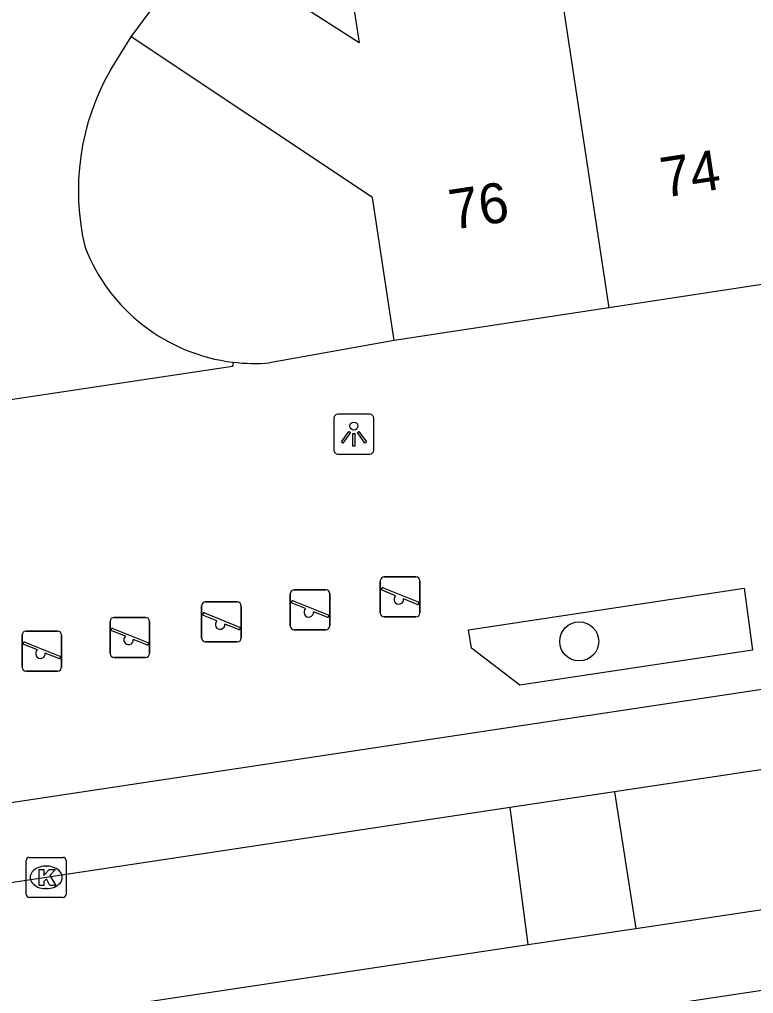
# Model space of a CAD drawing. Extents: x 159280 to 160375, y 384531 to 385872.
# Drawn here: x 159751.21 to 159769.6, y 384897.02 to 384921.41 of the extents above; entities that cross this region are included whole.
import ezdxf

# ---------------------------------------------------------------- set-up
doc = ezdxf.new("R2010")
doc.units = 0
for name, color, linetype in [('IMGEO_Boom', 7, 'Continuous'), ('IMGEO_Kolk', 7, 'Continuous'), ('IMGEO_Lichtpunt', 7, 'Continuous'), ('IMGEO_Pand', 7, 'Continuous'), ('IMGEO_Pand_nummerreeks', 7, 'Continuous'), ('IMGEO_Rijbaan_lokaal_open', 7, 'Continuous'), ('IMGEO_Speelvoorziening', 7, 'Continuous'), ('IMGEO_Voetpad_open', 7, 'Continuous')]:
    doc.layers.add(name, color=color, linetype=linetype)

msp = doc.modelspace()

# ---------------------------------------------------------------- linework, layer by layer
at = {"layer": 'IMGEO_Boom'}
msp.add_circle((159765.234, 384905.833), 0.489, dxfattribs=at)
at = {"layer": 'IMGEO_Kolk'}
for p, q in [((159751.383, 384899.5), (159751.383, 384900.352)), ((159751.458, 384900.426), (159752.31, 384900.426)), ((159752.384, 384900.352), (159752.384, 384899.5)), ((159751.871, 384900.206), (159751.896, 384900.206)), ((159751.894, 384899.646), (159751.869, 384899.646)), ((159752.31, 384899.426), (159751.458, 384899.426))]:
    msp.add_line(p, q, dxfattribs=at)
for points in [[(159751.383, 384899.5), (159751.383, 384900.352)], [(159751.458, 384900.426), (159752.31, 384900.426)], [(159752.384, 384900.352), (159752.384, 384899.5)], [(159751.704, 384900.126), (159751.827, 384900.126), (159751.827, 384899.975), (159751.957, 384900.126), (159752.121, 384900.126), (159751.975, 384899.975), (159752.128, 384899.726), (159751.976, 384899.726), (159751.891, 384899.89), (159751.827, 384899.823), (159751.827, 384899.726), (159751.704, 384899.726), (159751.704, 384900.126)], [(159752.31, 384899.426), (159751.458, 384899.426)]]:
    msp.add_lwpolyline(points, dxfattribs=at)
for centre, start, end in [((159751.46, 384900.35), 91.552, 178.448), ((159751.46, 384900.35), 91.552, 178.448), ((159752.308, 384900.35), 1.552, 88.448), ((159752.308, 384900.35), 1.552, 88.448), ((159751.46, 384899.502), 181.552, 268.448), ((159751.46, 384899.502), 181.552, 268.448), ((159752.308, 384899.502), 271.552, 358.448), ((159752.308, 384899.502), 271.552, 358.448)]:
    msp.add_arc(centre, 0.0765, start, end, dxfattribs=at)
for centre, major_axis, ratio, start_param, end_param in [((159751.87, 384899.926), (-0.387, 0.002), 0.722429, 4.712389, 7.853982), ((159751.895, 384899.926), (-0.39, 0.002), 0.717154, 1.570796, 4.712389)]:
    msp.add_ellipse(centre, major_axis=major_axis, ratio=ratio, start_param=start_param, end_param=end_param, dxfattribs=at)
at = {"layer": 'IMGEO_Lichtpunt'}
for p, q in [((159759.994, 384911.522), (159759.186, 384911.522)), ((159759.994, 384911.522), (159759.186, 384911.522)), ((159759.092, 384911.427), (159759.092, 384910.62)), ((159759.092, 384911.427), (159759.092, 384910.62)), ((159760.088, 384910.62), (159760.088, 384911.427)), ((159760.088, 384910.62), (159760.088, 384911.427)), ((159759.186, 384910.526), (159759.994, 384910.526)), ((159759.186, 384910.526), (159759.994, 384910.526))]:
    msp.add_line(p, q, dxfattribs=at)
for points in [[(159759.466, 384911.091), (159759.505, 384911.063), (159759.317, 384910.801), (159759.279, 384910.828), (159759.466, 384911.091)], [(159759.568, 384911.043), (159759.615, 384911.043), (159759.615, 384910.721), (159759.568, 384910.721), (159759.568, 384911.043)], [(159759.678, 384911.063), (159759.716, 384911.09), (159759.903, 384910.828), (159759.864, 384910.8), (159759.678, 384911.063)]]:
    msp.add_lwpolyline(points, dxfattribs=at)
msp.add_circle((159759.591, 384911.225), 0.0994, dxfattribs=at)
for centre, start, end in [((159759.186, 384911.427), 90, 180), ((159759.186, 384911.427), 90, 180), ((159759.994, 384911.427), 0, 90), ((159759.994, 384911.427), 0, 90), ((159759.186, 384910.62), 180, 270), ((159759.186, 384910.62), 180, 270), ((159759.994, 384910.62), 270, 0), ((159759.994, 384910.62), 270, 360)]:
    msp.add_arc(centre, 0.0946, start, end, dxfattribs=at)
at = {"layer": 'IMGEO_Pand'}
for points in [[(159764.393, 384924.608), (159764.205, 384924.579), (159759.261, 384923.827), (159759.719, 384920.818), (159755.775, 384923.361)], [(159764.393, 384924.608), (159764.83, 384921.733), (159765.976, 384914.186)], [(159754.013, 384920.967), (159755.775, 384923.361)], [(159760.601, 384913.369), (159760.056, 384916.949), (159754.013, 384920.967)], [(159771.234, 384914.986), (159765.976, 384914.186)], [(159765.976, 384914.186), (159760.601, 384913.369)]]:
    msp.add_lwpolyline(points, dxfattribs=at)
at = {"layer": 'IMGEO_Rijbaan_lokaal_open'}
for points in [[(159766.651, 384898.646), (159819.621, 384906.592)], [(159790.937, 384905.799), (159766.12, 384902.067)], [(159766.12, 384902.067), (159763.502, 384901.673)], [(159766.12, 384902.067), (159766.651, 384898.646)], [(159763.502, 384901.673), (159747.895, 384899.326)], [(159763.958, 384898.242), (159763.502, 384901.673)], [(159763.958, 384898.242), (159766.651, 384898.646)], [(159743.377, 384895.154), (159763.958, 384898.242)]]:
    msp.add_lwpolyline(points, dxfattribs=at)
at = {"layer": 'IMGEO_Speelvoorziening'}
for p, q in [((159760.253, 384906.549), (159760.253, 384907.349)), ((159760.253, 384907.349), (159760.253, 384906.549)), ((159760.353, 384907.449), (159761.143, 384907.449)), ((159761.143, 384907.449), (159760.353, 384907.449)), ((159761.243, 384907.349), (159761.243, 384906.549)), ((159761.243, 384906.549), (159761.243, 384907.349)), ((159758.098, 384907.127), (159758.888, 384907.127)), ((159758.888, 384907.127), (159758.098, 384907.127)), ((159760.636, 384906.977), (159760.297, 384907.114)), ((159760.322, 384907.174), (159761.198, 384906.821)), ((159755.878, 384906.821), (159756.668, 384906.821)), ((159756.668, 384906.821), (159755.878, 384906.821)), ((159757.998, 384906.227), (159757.998, 384907.027)), ((159757.998, 384907.027), (159757.998, 384906.227)), ((159758.067, 384906.852), (159758.943, 384906.499)), ((159758.988, 384907.027), (159758.988, 384906.227)), ((159758.988, 384906.227), (159758.988, 384907.027)), ((159761.174, 384906.761), (159760.834, 384906.898)), ((159755.778, 384905.921), (159755.778, 384906.721)), ((159755.778, 384906.721), (159755.778, 384905.921)), ((159756.768, 384906.721), (159756.768, 384905.921)), ((159756.768, 384905.921), (159756.768, 384906.721)), ((159758.381, 384906.655), (159758.042, 384906.792)), ((159758.919, 384906.439), (159758.579, 384906.576)), ((159753.484, 384905.535), (159753.484, 384906.335)), ((159753.484, 384906.335), (159753.484, 384905.535)), ((159753.584, 384906.435), (159754.374, 384906.435)), ((159754.374, 384906.435), (159753.584, 384906.435)), ((159754.474, 384906.335), (159754.474, 384905.535)), ((159754.474, 384905.535), (159754.474, 384906.335)), ((159756.161, 384906.349), (159755.822, 384906.486)), ((159755.847, 384906.546), (159756.723, 384906.193)), ((159761.143, 384906.449), (159760.353, 384906.449)), ((159760.353, 384906.449), (159761.143, 384906.449)), ((159751.379, 384906.092), (159752.169, 384906.092)), ((159752.169, 384906.092), (159751.379, 384906.092)), ((159753.867, 384905.963), (159753.528, 384906.1)), ((159753.553, 384906.16), (159754.429, 384905.807)), ((159756.699, 384906.133), (159756.359, 384906.27)), ((159758.888, 384906.127), (159758.098, 384906.127)), ((159758.098, 384906.127), (159758.888, 384906.127)), ((159751.279, 384905.192), (159751.279, 384905.992)), ((159751.279, 384905.992), (159751.279, 384905.192)), ((159752.269, 384905.992), (159752.269, 384905.192)), ((159752.269, 384905.192), (159752.269, 384905.992)), ((159754.405, 384905.747), (159754.065, 384905.884)), ((159751.662, 384905.62), (159751.323, 384905.757)), ((159751.348, 384905.817), (159752.224, 384905.464)), ((159756.668, 384905.821), (159755.878, 384905.821)), ((159755.878, 384905.821), (159756.668, 384905.821)), ((159752.2, 384905.404), (159751.86, 384905.541)), ((159754.374, 384905.435), (159753.584, 384905.435)), ((159753.584, 384905.435), (159754.374, 384905.435)), ((159752.169, 384905.092), (159751.379, 384905.092)), ((159751.379, 384905.092), (159752.169, 384905.092))]:
    msp.add_line(p, q, dxfattribs=at)
for centre, radius, start, end in [((159760.353, 384907.349), 0.1, 90, 180), ((159760.353, 384907.349), 0.1, 90, 180), ((159761.143, 384907.349), 0.1, 0, 90), ((159761.143, 384907.349), 0.1, 360, 90), ((159758.098, 384907.027), 0.1, 90, 180), ((159758.098, 384907.027), 0.1, 90, 180), ((159758.888, 384907.027), 0.1, 0, 90), ((159758.888, 384907.027), 0.1, 360, 90), ((159760.31, 384907.144), 0.0327, 68.078, 248.078), ((159755.878, 384906.721), 0.1, 90, 180), ((159755.878, 384906.721), 0.1, 90, 180), ((159756.668, 384906.721), 0.1, 0, 90), ((159756.668, 384906.721), 0.1, 360, 90), ((159758.055, 384906.822), 0.0327, 68.078, 248.078), ((159760.715, 384906.887), 0.12, 130.9928, 5.1632), ((159761.186, 384906.791), 0.0327, 248.078, 68.078), ((159758.46, 384906.565), 0.12, 130.9928, 5.1632), ((159753.584, 384906.335), 0.1, 90, 180), ((159753.584, 384906.335), 0.1, 90, 180), ((159754.374, 384906.335), 0.1, 0, 90), ((159754.374, 384906.335), 0.1, 360, 90), ((159755.835, 384906.516), 0.0327, 68.078, 248.078), ((159756.24, 384906.259), 0.12, 130.9928, 5.1632), ((159758.931, 384906.469), 0.0327, 248.078, 68.078), ((159760.353, 384906.549), 0.1, 180, 270), ((159760.353, 384906.549), 0.1, 180, 270), ((159761.143, 384906.549), 0.1, 270, 0), ((159761.143, 384906.549), 0.1, 270, 0), ((159751.379, 384905.992), 0.1, 90, 180), ((159751.379, 384905.992), 0.1, 90, 180), ((159752.169, 384905.992), 0.1, 0, 90), ((159752.169, 384905.992), 0.1, 360, 90), ((159753.541, 384906.13), 0.0327, 68.078, 248.078), ((159756.711, 384906.163), 0.0327, 248.078, 68.078), ((159758.098, 384906.227), 0.1, 180, 270), ((159758.098, 384906.227), 0.1, 180, 270), ((159758.888, 384906.227), 0.1, 270, 0), ((159758.888, 384906.227), 0.1, 270, 0), ((159753.946, 384905.873), 0.12, 130.9928, 5.1632), ((159755.878, 384905.921), 0.1, 180, 270), ((159755.878, 384905.921), 0.1, 180, 270), ((159756.668, 384905.921), 0.1, 270, 0), ((159756.668, 384905.921), 0.1, 270, 0), ((159751.336, 384905.787), 0.0327, 68.078, 248.078), ((159751.741, 384905.53), 0.12, 130.9928, 5.1632), ((159754.417, 384905.777), 0.0327, 248.078, 68.078), ((159752.212, 384905.434), 0.0327, 248.078, 68.078), ((159753.584, 384905.535), 0.1, 180, 270), ((159753.584, 384905.535), 0.1, 180, 270), ((159754.374, 384905.535), 0.1, 270, 0), ((159754.374, 384905.535), 0.1, 270, 0), ((159751.379, 384905.192), 0.1, 180, 270), ((159751.379, 384905.192), 0.1, 180, 270), ((159752.169, 384905.192), 0.1, 270, 0), ((159752.169, 384905.192), 0.1, 270, 0)]:
    msp.add_arc(centre, radius, start, end, dxfattribs=at)
at = {"layer": 'IMGEO_Voetpad_open'}
for points in [[(159753.492, 384920.137), (159754.013, 384920.967)], [(159760.601, 384913.369), (159757.477, 384912.807)], [(159756.564, 384912.825), (159756.548, 384912.717), (159748.702, 384911.539)], [(159748.286, 384901.388), (159789.944, 384907.679)], [(159769.368, 384907.165), (159769.575, 384905.619), (159763.749, 384904.742), (159762.537, 384905.669), (159762.46, 384906.127), (159769.368, 384907.165)], [(159744.327, 384893.267), (159819.28, 384904.555)]]:
    msp.add_lwpolyline(points, dxfattribs=at)
for centre, radius, start, end in [((159758.777, 384917.117), 6.088, 150.2548, 193.4959), ((159757.11, 384917.357), 4.565, 201.3366, 263.1343), ((159757.11, 384917.335), 4.542, 263.1017, 274.6394)]:
    msp.add_arc(centre, radius, start, end, dxfattribs=at)

# ---------------------------------------------------------------- texts
at = {"layer": 'IMGEO_Pand_nummerreeks'}
for s, p in [('74', (159767.351, 384916.943)), ('76', (159762.054, 384916.138))]:
    msp.add_text(s, height=1, rotation=8.6459, dxfattribs=at).set_placement(p)

doc.saveas('drawing.dxf')
